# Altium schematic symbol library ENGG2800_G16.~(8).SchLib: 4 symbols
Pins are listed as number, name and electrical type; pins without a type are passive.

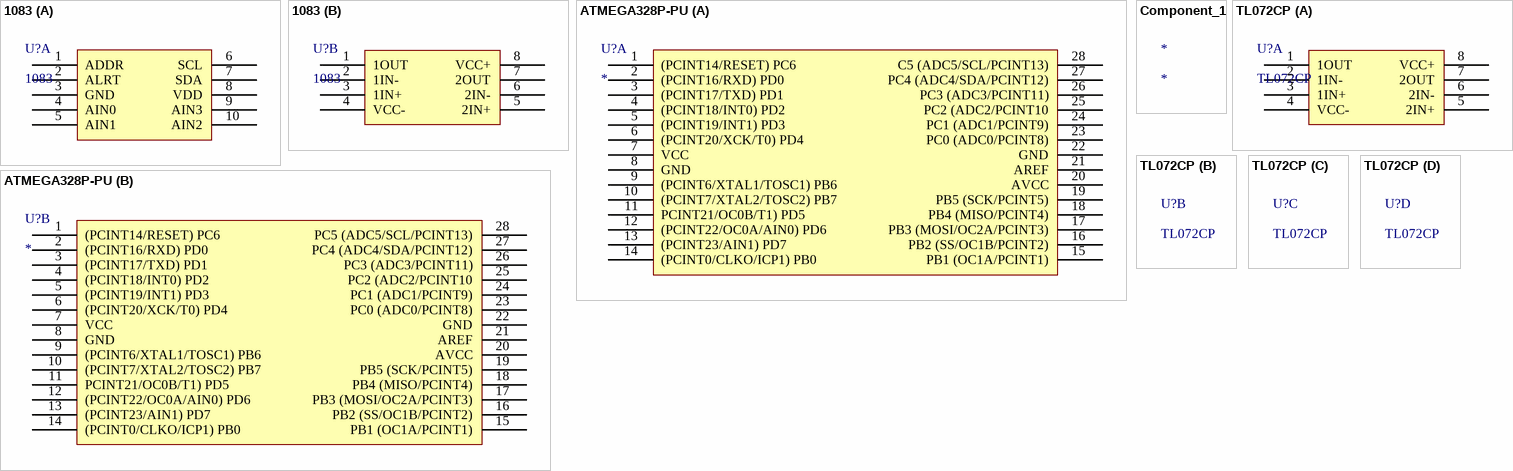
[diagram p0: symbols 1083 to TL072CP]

## 1083
designator U?
EVAL BOARD ADS1115 16-BIT ADC; Manufacturer: Adafruit Industries; Description: EVAL BOARD ADS1015 12-BIT ADC; Number of Bits: 12; Evaluation Kit: Yes; Number of A/D Converters: 1; Sampling Rate: 3300S/s; Interface: I2C,Serial
part A pins: 1 ADDR, 2 ALRT, 3 GND, 4 AIN0, 5 AIN1, 6 SCL, 7 SDA, 8 VDD, 9 AIN3, 10 AIN2
part B pins: 1 1OUT, 2 1IN-, 3 1IN+, 4 VCC-, 5 2IN+, 6 2IN-, 7 2OUT, 8 VCC+

## ATMEGA328P-PU
designator U?
IC MCU 8BIT 32KB FLASH 28DIP; Manufacturer: Microchip / Atmel; Manufacturer Part Number: ATMEGA328P-PU; Core Architecture: AVR; RAM Size: 2KB; Number of PWM Channels: 6; Number of Timers/Counters: 3; Min Supply Voltage: 1.8V; Max Supply Voltage: 5.5V; Interface: I2C,SPI,UART,USART,2-Wire; Number of I/Os: 23; Frequency: 20MHz; Oscillator Type: Internal; Data Bus Width: 8b; Number of SPI Channels: 1; Watchdog Timer: Yes; Peripherals: Brown-out Detect/Reset,POR,PWM,WDT
part A pins: 1 (PCINT14/RESET) PC6, 2 (PCINT16/RXD) PD0, 3 (PCINT17/TXD) PD1, 4 (PCINT18/INT0) PD2, 5 (PCINT19/INT1) PD3, 6 (PCINT20/XCK/T0) PD4, 7 VCC, 8 GND, 9 (PCINT6/XTAL1/TOSC1) PB6, 10 (PCINT7/XTAL2/TOSC2) PB7, 11 PCINT21/OC0B/T1) PD5, 12 (PCINT22/OC0A/AIN0) PD6, 13 (PCINT23/AIN1) PD7, 14 (PCINT0/CLKO/ICP1) PB0, 15 PB1 (OC1A/PCINT1), 16 PB2 (SS/OC1B/PCINT2), 17 PB3 (MOSI/OC2A/PCINT3), 18 PB4 (MISO/PCINT4), 19 PB5 (SCK/PCINT5), 20 AVCC, 21 AREF, 22 GND, 23 PC0 (ADC0/PCINT8), 24 PC1 (ADC1/PCINT9), 25 PC2 (ADC2/PCINT10, 26 PC3 (ADC3/PCINT11), 27 PC4 (ADC4/SDA/PCINT12), 28 C5 (ADC5/SCL/PCINT13)
part B pins: 1 (PCINT14/RESET) PC6, 2 (PCINT16/RXD) PD0, 3 (PCINT17/TXD) PD1, 4 (PCINT18/INT0) PD2, 5 (PCINT19/INT1) PD3, 6 (PCINT20/XCK/T0) PD4, 7 VCC, 8 GND, 9 (PCINT6/XTAL1/TOSC1) PB6, 10 (PCINT7/XTAL2/TOSC2) PB7, 11 PCINT21/OC0B/T1) PD5, 12 (PCINT22/OC0A/AIN0) PD6, 13 (PCINT23/AIN1) PD7, 14 (PCINT0/CLKO/ICP1) PB0, 15 PB1 (OC1A/PCINT1), 16 PB2 (SS/OC1B/PCINT2), 17 PB3 (MOSI/OC2A/PCINT3), 18 PB4 (MISO/PCINT4), 19 PB5 (SCK/PCINT5), 20 AVCC, 21 AREF, 22 GND, 23 PC0 (ADC0/PCINT8), 24 PC1 (ADC1/PCINT9), 25 PC2 (ADC2/PCINT10, 26 PC3 (ADC3/PCINT11), 27 PC4 (ADC4/SDA/PCINT12), 28 PC5 (ADC5/SCL/PCINT13)

## Component_1
designator *

## TL072CP
designator U?
IC, OP AMP, DUAL JFET, DIP8; Bandwidth:3MHz; No. of Amplifiers:2; Slew Rate:13V/ s; Supply Voltage Range:7V to 36V; Amplifier Case Style:DIP; No. of Pins:8; Operating Temperature Min:0 C; Operating Temperature Max:70 C; ;RoHS Compliant: Yes; Manufacturer: Texas Instruments; Bandwidth: 3MHz; Number of Channels: 2; Voltage Gain: 106.02dB; Nominal Supply Current: 5mA; Max Supply Voltage: 18V; Min Dual Supply Voltage: 3.5V; Dual Supply Voltage: 9V; Common Mode Rejection Ratio: 70dB; Slew Rate: 13V/µs; Max I/O Voltage: 10mV; Input Bias Current: 200pA; Input Offset Voltage (Vos): 3mV; Operating Supply Current: 1.4mA
part A pins: 1 1OUT, 2 1IN-, 3 1IN+, 4 VCC-, 5 2IN+, 6 2IN-, 7 2OUT, 8 VCC+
